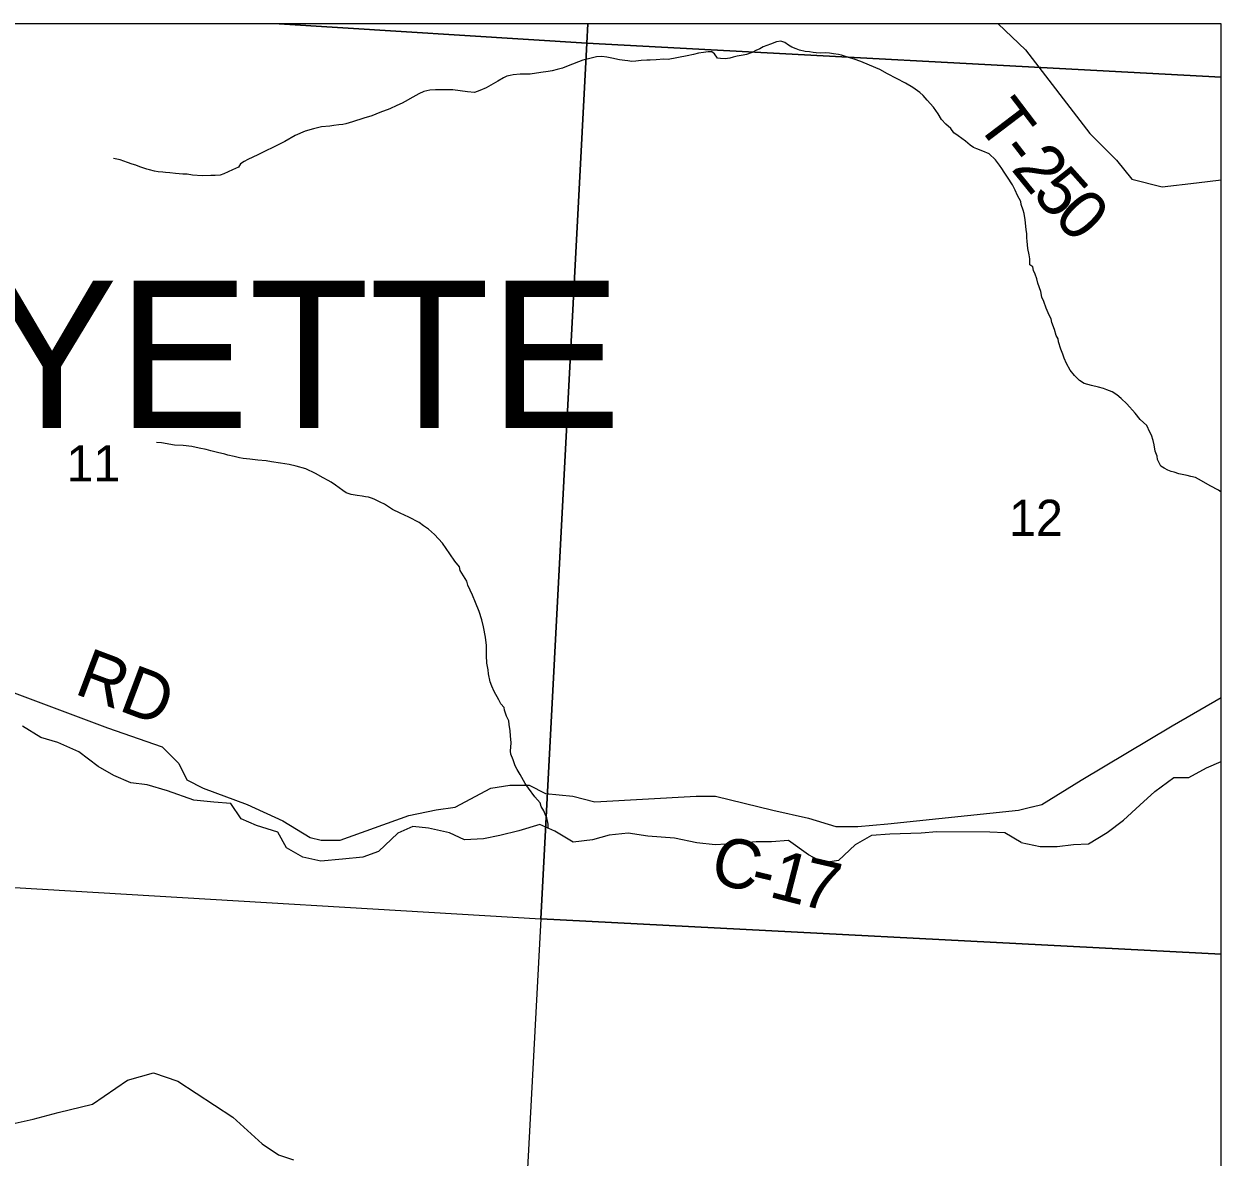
# Model space of a CAD drawing. Extents: x 1949938.81 to 1949945.61, y 152207.65 to 152214.09.
# Drawn here: x 1949944.221 to 1949945.607, y 152212.776 to 152214.087 of the extents above; entities that cross this region are included whole.
import ezdxf

# ---------------------------------------------------------------- set-up
doc = ezdxf.new("R2010")
doc.units = 0
for name, color, linetype in [('GM_X_County', 7, 'Continuous'), ('GM_X_County_Road', 7, 'Continuous'), ('GM_X_County_Road_Text', 7, 'Continuous'), ('GM_X_Minor_River', 7, 'Continuous'), ('GM_X_Section', 7, 'Continuous'), ('GM_X_Section_Text', 7, 'Continuous'), ('GM_X_Township', 7, 'Continuous'), ('GM_X_Township_Road', 7, 'Continuous'), ('GM_X_Township_Road_Text', 7, 'Continuous'), ('GM_X_Township_ROW', 7, 'Continuous'), ('GM_X_Township_Text', 7, 'Continuous')]:
    doc.layers.add(name, color=color, linetype=linetype)

msp = doc.modelspace()

# ---------------------------------------------------------------- linework, layer by layer
at = {"layer": 'GM_X_County'}
msp.add_lwpolyline([(1949945.6069, 152208.8266), (1949945.6069, 152214.0874), (1949938.8069, 152214.0874), (1949938.8069, 152213.1813)], dxfattribs=at)
at = {"layer": 'GM_X_County_Road'}
for points in [[(1949944.1914, 152213.3205), (1949944.3181, 152213.2729), (1949944.3815, 152213.2508), (1949944.4005, 152213.2317), (1949944.41, 152213.2127), (1949944.429, 152213.2032), (1949944.4797, 152213.1842), (1949944.5209, 152213.1652), (1949944.5526, 152213.1462), (1949944.5653, 152213.143), (1949944.5875, 152213.143), (1949944.6667, 152213.1715), (1949944.6984, 152213.1779), (1949944.7206, 152213.181), (1949944.7617, 152213.2032), (1949944.7839, 152213.2064), (1949944.8061, 152213.2064), (1949944.8251, 152213.1969), (1949944.8568, 152213.1937), (1949944.8822, 152213.1874), (1949944.9994, 152213.1937), (1949945.0216, 152213.1937), (1949945.0881, 152213.1778), (1949945.1293, 152213.1683), (1949945.161, 152213.1588), (1949945.1864, 152213.1588), (1949945.2212, 152213.162), (1949945.3725, 152213.1775), (1949945.3879, 152213.1815), (1949945.3882, 152213.1816)], [(1949945.3882, 152213.1816), (1949945.3994, 152213.1844), (1949945.4448, 152213.2122), (1949945.5504, 152213.2754), (1949945.6069, 152213.308)]]:
    msp.add_lwpolyline(points, dxfattribs=at)
at = {"layer": 'GM_X_Minor_River'}
for points in [[(1949945.3503, 152213.9241), (1949945.3459, 152213.9302), (1949945.3384, 152213.9372), (1949945.3313, 152213.94), (1949945.3241, 152213.9428), (1949945.3204, 152213.9443), (1949945.3166, 152213.9471), (1949945.311, 152213.9517), (1949945.3028, 152213.9579), (1949945.2976, 152213.9614), (1949945.2943, 152213.9664), (1949945.2883, 152213.9715), (1949945.2835, 152213.9769), (1949945.2794, 152213.9834), (1949945.2739, 152213.9911), (1949945.2668, 152213.9992), (1949945.262, 152214.0046), (1949945.2582, 152214.008), (1949945.25, 152214.0139), (1949945.2418, 152214.019), (1949945.2313, 152214.0241), (1949945.2208, 152214.0296), (1949945.2118, 152214.0347), (1949945.2001, 152214.0398), (1949945.1899, 152214.0438), (1949945.1824, 152214.0465), (1949945.176, 152214.0486), (1949945.1722, 152214.0498), (1949945.1677, 152214.0514), (1949945.1643, 152214.0522), (1949945.1583, 152214.053), (1949945.1538, 152214.0535), (1949945.1496, 152214.0539), (1949945.1435, 152214.0537), (1949945.1382, 152214.0541), (1949945.1348, 152214.0542), (1949945.1307, 152214.055), (1949945.1254, 152214.0555), (1949945.119, 152214.0571), (1949945.1152, 152214.0587), (1949945.1103, 152214.0607), (1949945.1062, 152214.063), (1949945.1021, 152214.0661), (1949945.0972, 152214.0674), (1949945.0922, 152214.0667), (1949945.0854, 152214.0641), (1949945.077, 152214.0609), (1949945.0732, 152214.0587), (1949945.0686, 152214.0565), (1949945.0644, 152214.0543), (1949945.0575, 152214.0521), (1949945.0537, 152214.0514), (1949945.0469, 152214.05), (1949945.0423, 152214.0489), (1949945.0385, 152214.0479), (1949945.0328, 152214.0472), (1949945.0275, 152214.0473), (1949945.0241, 152214.0477), (1949945.0208, 152214.0527), (1949945.0174, 152214.0551), (1949945.0133, 152214.0551), (1949945.0079, 152214.0545), (1949945.0022, 152214.0534), (1949944.9962, 152214.052), (1949944.9889, 152214.0506), (1949944.9669, 152214.0464), (1949944.962, 152214.0465), (1949944.9533, 152214.0459), (1949944.946, 152214.0456), (1949944.9423, 152214.0453), (1949944.9358, 152214.045), (1949944.9294, 152214.0444), (1949944.9248, 152214.0441), (1949944.9203, 152214.0446), (1949944.9169, 152214.045), (1949944.9108, 152214.0459), (1949944.9018, 152214.0479), (1949944.8961, 152214.0488), (1949944.8901, 152214.0496), (1949944.884, 152214.0493), (1949944.8764, 152214.0476), (1949944.8684, 152214.0454), (1949944.8512, 152214.0389), (1949944.8448, 152214.0363), (1949944.8387, 152214.0346), (1949944.8326, 152214.0331), (1949944.828, 152214.0325), (1949944.8197, 152214.0311), (1949944.8071, 152214.0294), (1949944.7958, 152214.0292), (1949944.7878, 152214.0286), (1949944.784, 152214.0279), (1949944.7802, 152214.0268), (1949944.7764, 152214.025), (1949944.7699, 152214.0213), (1949944.7565, 152214.0135), (1949944.7492, 152214.0103), (1949944.7427, 152214.0081), (1949944.7348, 152214.009), (1949944.7178, 152214.0112), (1949944.6977, 152214.0111)], [(1949944.6977, 152214.0111), (1949944.6913, 152214.0109), (1949944.6844, 152214.0091), (1949944.6783, 152214.0065), (1949944.6714, 152214.0028), (1949944.6626, 152213.9977), (1949944.6592, 152213.9958), (1949944.6531, 152213.9929), (1949944.6447, 152213.9893), (1949944.6333, 152213.9849), (1949944.6241, 152213.9812), (1949944.6146, 152213.9784), (1949944.6016, 152213.974), (1949944.594, 152213.9719), (1949944.5906, 152213.9712), (1949944.586, 152213.9705), (1949944.58, 152213.9699), (1949944.5754, 152213.9692), (1949944.5659, 152213.9682), (1949944.5564, 152213.9661), (1949944.5469, 152213.9632), (1949944.5354, 152213.9585), (1949944.5232, 152213.9515), (1949944.5148, 152213.947), (1949944.5087, 152213.9441), (1949944.5022, 152213.9408), (1949944.4922, 152213.936), (1949944.4804, 152213.9305), (1949944.4762, 152213.9283), (1949944.472, 152213.9257), (1949944.4696, 152213.9216), (1949944.4628, 152213.9187), (1949944.4528, 152213.9139), (1949944.4487, 152213.9125), (1949944.4426, 152213.9122), (1949944.4377, 152213.9119), (1949944.4278, 152213.9117), (1949944.4165, 152213.9126), (1949944.4104, 152213.9135), (1949944.4055, 152213.9136), (1949944.401, 152213.914), (1949944.3968, 152213.9145), (1949944.3904, 152213.915), (1949944.3854, 152213.9154), (1949944.382, 152213.9159), (1949944.3768, 152213.9164), (1949944.3726, 152213.9172), (1949944.3669, 152213.9184), (1949944.3635, 152213.9192), (1949944.3556, 152213.922), (1949944.3511, 152213.924), (1949944.3466, 152213.9252), (1949944.3413, 152213.9272), (1949944.3327, 152213.93), (1949944.3251, 152213.9317)], [(1949945.6069, 152213.5457), (1949945.6039, 152213.548), (1949945.5941, 152213.5528), (1949945.5844, 152213.5586), (1949945.5773, 152213.5625), (1949945.572, 152213.5638), (1949945.5675, 152213.565), (1949945.558, 152213.567), (1949945.5524, 152213.5687), (1949945.549, 152213.5695), (1949945.5452, 152213.5711), (1949945.5411, 152213.5734), (1949945.5373, 152213.5757), (1949945.5333, 152213.5834), (1949945.533, 152213.5872), (1949945.5305, 152213.5929), (1949945.5294, 152213.6002), (1949945.5284, 152213.6055), (1949945.5262, 152213.6116), (1949945.5244, 152213.6151), (1949945.5211, 152213.6227), (1949945.5133, 152213.6297), (1949945.5074, 152213.637), (1949945.4977, 152213.6478), (1949945.4914, 152213.654), (1949945.4862, 152213.6583), (1949945.4809, 152213.6618), (1949945.4745, 152213.6641), (1949945.4708, 152213.6657), (1949945.4651, 152213.667), (1949945.4568, 152213.669), (1949945.4485, 152213.6714), (1949945.4429, 152213.6749), (1949945.4373, 152213.6807), (1949945.4321, 152213.6869), (1949945.4281, 152213.6946), (1949945.4252, 152213.7007), (1949945.4237, 152213.7053), (1949945.4216, 152213.711), (1949945.4187, 152213.7194), (1949945.4184, 152213.7232), (1949945.4162, 152213.727), (1949945.414, 152213.7339), (1949945.4111, 152213.7419), (1949945.4101, 152213.7461), (1949945.4079, 152213.7503), (1949945.4046, 152213.7584), (1949945.4017, 152213.7664), (1949945.3995, 152213.7714), (1949945.3981, 152213.7778), (1949945.3949, 152213.7874), (1949945.3935, 152213.7923), (1949945.3917, 152213.7977), (1949945.3898, 152213.8023), (1949945.3892, 152213.8065), (1949945.3854, 152213.8088), (1949945.3855, 152213.8156), (1949945.3849, 152213.8202), (1949945.3831, 152213.8275), (1949945.3825, 152213.8362), (1949945.3822, 152213.84), (1949945.3819, 152213.8449), (1949945.3812, 152213.8491), (1949945.3806, 152213.8571), (1949945.3803, 152213.8609), (1949945.3789, 152213.8682), (1949945.3778, 152213.872), (1949945.3757, 152213.8785), (1949945.3753, 152213.8819), (1949945.3713, 152213.8888), (1949945.3687, 152213.8949), (1949945.3655, 152213.9014), (1949945.3599, 152213.9102), (1949945.3559, 152213.916), (1949945.3533, 152213.9202), (1949945.3503, 152213.9241)], [(1949944.8281, 152213.1564), (1949944.8282, 152213.1613), (1949944.8265, 152213.1689), (1949944.8246, 152213.1731), (1949944.8232, 152213.177), (1949944.8199, 152213.182), (1949944.8188, 152213.1862), (1949944.8125, 152213.1931), (1949944.8055, 152213.2031), (1949944.8014, 152213.2085), (1949944.7959, 152213.2188), (1949944.7922, 152213.2246), (1949944.79, 152213.2288), (1949944.7875, 152213.236), (1949944.7849, 152213.2425), (1949944.7846, 152213.246), (1949944.7852, 152213.2555), (1949944.7846, 152213.2638), (1949944.7843, 152213.2695), (1949944.7829, 152213.2768), (1949944.7826, 152213.2809), (1949944.78, 152213.2863), (1949944.7775, 152213.2932), (1949944.7772, 152213.2966), (1949944.7735, 152213.3008), (1949944.7709, 152213.3054), (1949944.7658, 152213.315), (1949944.7629, 152213.3211), (1949944.761, 152213.3261), (1949944.7589, 152213.3356), (1949944.7586, 152213.3402), (1949944.7573, 152213.3478), (1949944.7567, 152213.3566), (1949944.7569, 152213.3683), (1949944.7555, 152213.3778), (1949944.7531, 152213.3897), (1949944.7513, 152213.398), (1949944.7481, 152213.4076), (1949944.7441, 152213.4179), (1949944.7405, 152213.4263), (1949944.735, 152213.4382), (1949944.7339, 152213.4428), (1949944.7262, 152213.455), (1949944.7255, 152213.4592), (1949944.72, 152213.4658), (1949944.7144, 152213.4742), (1949944.7059, 152213.4865), (1949944.6966, 152213.4966), (1949944.6895, 152213.5027), (1949944.6839, 152213.5066), (1949944.6787, 152213.5105), (1949944.6667, 152213.5168), (1949944.6569, 152213.5215), (1949944.6479, 152213.5255), (1949944.6389, 152213.5317), (1949944.6337, 152213.5341), (1949944.6269, 152213.5376), (1949944.6235, 152213.5388), (1949944.6201, 152213.54), (1949944.6167, 152213.5404), (1949944.613, 152213.5409), (1949944.6069, 152213.5417), (1949944.6001, 152213.543), (1949944.5945, 152213.545), (1949944.5903, 152213.5477), (1949944.5821, 152213.5536), (1949944.5769, 152213.5571), (1949944.5735, 152213.559), (1949944.5679, 152213.5622), (1949944.5589, 152213.5672), (1949944.5476, 152213.5728), (1949944.5363, 152213.5756), (1949944.5284, 152213.5776), (1949944.5182, 152213.5793), (1949944.508, 152213.5806), (1949944.5016, 152213.5819), (1949944.4921, 152213.5828), (1949944.483, 152213.5837), (1949944.4751, 152213.5846), (1949944.4709, 152213.5854), (1949944.4649, 152213.5867), (1949944.4574, 152213.5883), (1949944.454, 152213.5895), (1949944.4453, 152213.5916), (1949944.4378, 152213.5936), (1949944.4325, 152213.5948), (1949944.4242, 152213.5965), (1949944.4159, 152213.5985), (1949944.4057, 152213.5998), (1949944.3958, 152213.6), (1949944.3807, 152213.6026), (1949944.3747, 152213.603)], [(1949945.3757, 152213.1404), (1949945.3568, 152213.1515), (1949945.3394, 152213.1523), (1949945.2781, 152213.1526), (1949945.2599, 152213.1511), (1949945.2235, 152213.1497), (1949945.2023, 152213.1483), (1949945.1833, 152213.1377), (1949945.1643, 152213.1196), (1949945.1469, 152213.1166), (1949945.1295, 152213.1258), (1949945.1061, 152213.1426), (1949945.0864, 152213.1411), (1949945.069, 152213.1412), (1949945.047, 152213.139), (1949945.0212, 152213.1376), (1949945.0001, 152213.1399), (1949944.9743, 152213.1453), (1949944.9433, 152213.1477), (1949944.9206, 152213.1509), (1949944.8986, 152213.1487), (1949944.8796, 152213.1434), (1949944.8569, 152213.1405), (1949944.8358, 152213.1534), (1949944.8184, 152213.1611), (1949944.7941, 152213.1536), (1949944.7721, 152213.1484), (1949944.7532, 152213.1446), (1949944.7312, 152213.1432), (1949944.7138, 152213.1516), (1949944.6896, 152213.157), (1949944.6714, 152213.1586), (1949944.654, 152213.1511), (1949944.6319, 152213.1299), (1949944.6137, 152213.1231), (1949944.5902, 152213.121), (1949944.5652, 152213.1188), (1949944.5441, 152213.1234), (1949944.5252, 152213.1341), (1949944.5154, 152213.1523), (1949944.4904, 152213.16), (1949944.473, 152213.1677), (1949944.461, 152213.1852), (1949944.4413, 152213.1868), (1949944.4179, 152213.1891), (1949944.3876, 152213.1999), (1949944.3642, 152213.2068), (1949944.3452, 152213.2091), (1949944.3256, 152213.2176), (1949944.3074, 152213.2283), (1949944.2848, 152213.245), (1949944.2606, 152213.2558), (1949944.2409, 152213.2619), (1949944.2198, 152213.2749)], [(1949945.3757, 152213.1404), (1949945.3976, 152213.1358), (1949945.4173, 152213.1358), (1949945.4362, 152213.1381), (1949945.4536, 152213.1388), (1949945.4749, 152213.1517), (1949945.4938, 152213.1661), (1949945.5128, 152213.1835), (1949945.5302, 152213.1994), (1949945.5522, 152213.2153), (1949945.5696, 152213.2153), (1949945.59, 152213.2267), (1949945.6069, 152213.2338)]]:
    msp.add_lwpolyline(points, dxfattribs=at)
at = {"layer": 'GM_X_Section'}
for p, q in [((1949944.5169, 152214.0874), (1949943.7893, 152214.0874)), ((1949944.8742, 152214.0874), (1949944.5169, 152214.0874)), ((1949945.6069, 152213.0111), (1949945.6069, 152214.0257)), ((1949945.6069, 152211.9807), (1949945.6069, 152213.0111))]:
    msp.add_line(p, q, dxfattribs=at)
for points in [[(1949943.7893, 152214.0874), (1949943.7308, 152213.1166), (1949944.8197, 152213.0519), (1949944.873, 152214.065), (1949944.5169, 152214.0874)], [(1949944.5169, 152214.0874), (1949944.873, 152214.065), (1949944.8742, 152214.0874)], [(1949944.8742, 152214.0874), (1949944.873, 152214.065), (1949945.6069, 152214.0257)], [(1949945.6069, 152214.0257), (1949945.6069, 152214.0874), (1949944.8742, 152214.0874)], [(1949945.6069, 152214.0257), (1949944.873, 152214.065), (1949944.8197, 152213.0519), (1949945.6069, 152213.0111)], [(1949945.6069, 152213.0111), (1949944.8197, 152213.0519), (1949944.7648, 152212.0263), (1949945.6069, 152211.9807)]]:
    msp.add_lwpolyline(points, dxfattribs=at)
msp.add_lwpolyline([(1949944.8197, 152213.0519), (1949944.7648, 152212.0263), (1949943.6665, 152212.0918), (1949943.7308, 152213.1166)], close=True, dxfattribs=at)
at = {"layer": 'GM_X_Township'}
msp.add_lwpolyline([(1949945.6069, 152208.8266), (1949945.6069, 152214.0874), (1949942.6839, 152214.0874)], dxfattribs=at)
at = {"layer": 'GM_X_Township_Road'}
msp.add_lwpolyline([(1949945.349, 152214.0874), (1949945.3804, 152214.0573), (1949945.4551, 152213.9606), (1949945.4859, 152213.9298), (1949945.5035, 152213.9078), (1949945.5387, 152213.899), (1949945.5783, 152213.9034), (1949945.6069, 152213.907)], dxfattribs=at)
at = {"layer": 'GM_X_Township_ROW'}
msp.add_lwpolyline([(1949944.1905, 152212.8179), (1949944.2114, 152212.8155), (1949944.2323, 152212.8203), (1949944.2612, 152212.828), (1949944.3009, 152212.8376), (1949944.3412, 152212.8652), (1949944.3713, 152212.8736), (1949944.3994, 152212.8639), (1949944.463, 152212.8223), (1949944.4973, 152212.7917), (1949944.5162, 152212.779), (1949944.5333, 152212.7731)], dxfattribs=at)

# ---------------------------------------------------------------- texts
at = {"layer": 'GM_X_County_Road_Text'}
for s, height, rotation, p in [('RD', 0.05682, 339.3866, (1949944.2782, 152213.313)), ('C', 0.0568, 345.0772, (1949945.0131, 152213.0956)), ('1', 0.0568, 345.5731, (1949945.0821, 152213.0778)), ('7', 0.0568, 346.8992, (1949945.1174, 152213.0687)), ('-', 0.0568, 346.4803, (1949945.0597, 152213.0832))]:
    msp.add_text(s, height=height, rotation=rotation, dxfattribs=at).set_placement(p)
at = {"layer": 'GM_X_Section_Text'}
for s, p in [('11', (1949944.2707, 152213.558)), ('12', (1949945.3615, 152213.495))]:
    msp.add_text(s, height=0.04186, rotation=0, dxfattribs=at).set_placement(p)
at = {"layer": 'GM_X_Township_Road_Text'}
for s, rotation, p in [('T', 307.2374, (1949945.3217, 152213.9733)), ('-', 307.6766, (1949945.3477, 152213.9391)), ('2', 308.9803, (1949945.3629, 152213.9196)), ('5', 311.694, (1949945.3868, 152213.8901)), ('0', 313.4766, (1949945.4114, 152213.8626))]:
    msp.add_text(s, height=0.0568, rotation=rotation, dxfattribs=at).set_placement(p)
at = {"layer": 'GM_X_Township_Text'}
msp.add_text('FAYETTE', height=0.17045, rotation=0, dxfattribs=at).set_placement((1949943.8866, 152213.62))

doc.saveas('drawing.dxf')
